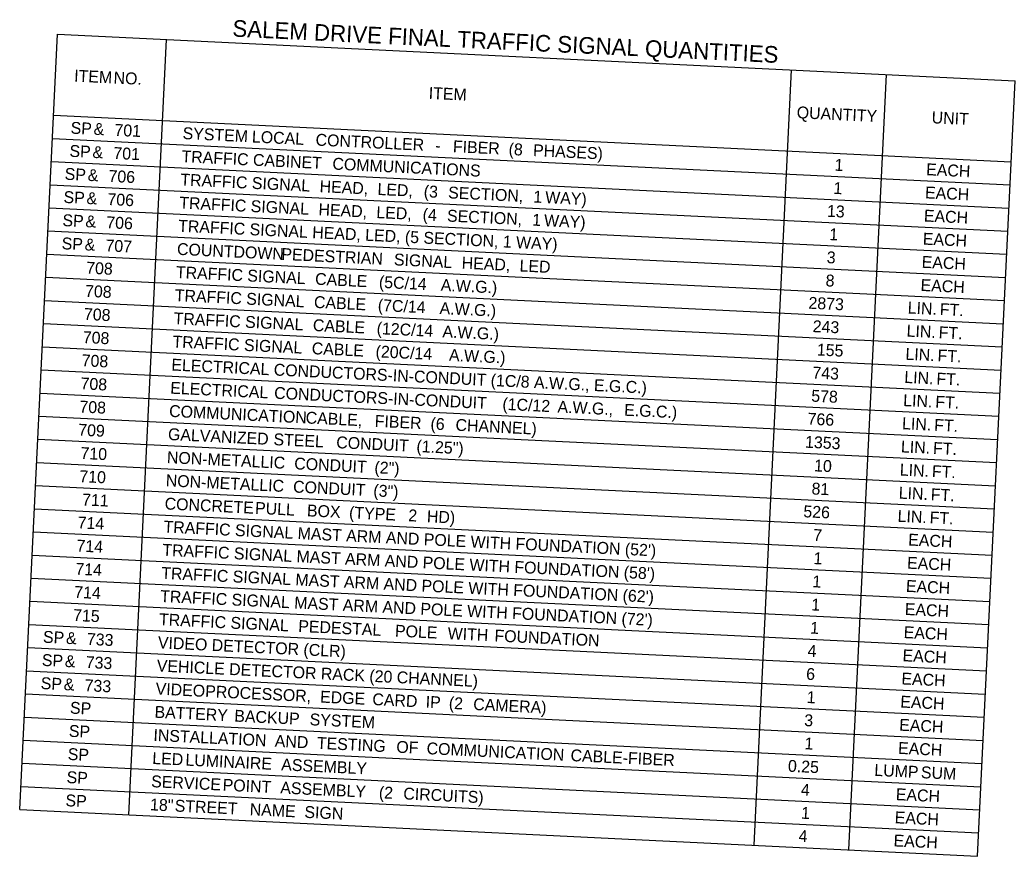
# Model space of a CAD drawing. Extents: x 661018 to 663325, y 642537 to 643074.
# Drawn here: x 661242.6 to 661445.4, y 642615.8 to 642786.2 of the extents above; entities that cross this region are included whole.
import ezdxf

# ---------------------------------------------------------------- set-up
doc = ezdxf.new("R2010")
doc.units = 0
doc.layers.add('R_Border Notes', color=7, linetype='Continuous')

msp = doc.modelspace()

# ---------------------------------------------------------------- linework, layer by layer
at = {"layer": 'R_Border Notes'}
for p, q in [((661242.61, 642625.3), (661250.28, 642783.32)), ((661250.28, 642783.32), (661445.37, 642773.84)), ((661264.78, 642624.22), (661272.45, 642782.24)), ((661392.18, 642618.03), (661399.85, 642776.05)), ((661411.52, 642617.09), (661419.19, 642775.11)), ((661437.7, 642615.82), (661445.37, 642773.84)), ((661249.48, 642766.81), (661444.57, 642757.33)), ((661249.25, 642762.09), (661444.34, 642752.62)), ((661249.02, 642757.37), (661444.11, 642747.9)), ((661248.79, 642752.65), (661443.88, 642743.18)), ((661248.56, 642747.94), (661443.65, 642738.46)), ((661248.33, 642743.22), (661443.43, 642733.75)), ((661248.11, 642738.5), (661443.2, 642729.03)), ((661247.88, 642733.79), (661442.97, 642724.31)), ((661247.65, 642729.07), (661442.74, 642719.6)), ((661247.42, 642724.35), (661442.51, 642714.88)), ((661247.19, 642719.64), (661442.28, 642710.16)), ((661246.96, 642714.92), (661442.05, 642705.45)), ((661246.73, 642710.2), (661441.82, 642700.73)), ((661246.5, 642705.48), (661441.59, 642696.01)), ((661246.27, 642700.77), (661441.36, 642691.29)), ((661246.04, 642696.05), (661441.14, 642686.58)), ((661245.82, 642691.33), (661440.91, 642681.86)), ((661245.59, 642686.62), (661440.68, 642677.14)), ((661245.36, 642681.9), (661440.45, 642672.43)), ((661245.13, 642677.18), (661440.22, 642667.71)), ((661244.9, 642672.47), (661439.99, 642662.99)), ((661244.67, 642667.75), (661439.76, 642658.28)), ((661244.44, 642663.03), (661439.53, 642653.56)), ((661244.21, 642658.31), (661439.3, 642648.84)), ((661243.98, 642653.6), (661439.07, 642644.12)), ((661243.75, 642648.88), (661438.84, 642639.41)), ((661243.52, 642644.16), (661438.62, 642634.69)), ((661243.3, 642639.45), (661438.39, 642629.97)), ((661243.07, 642634.73), (661438.16, 642625.26)), ((661242.84, 642630.01), (661437.93, 642620.54)), ((661242.61, 642625.3), (661437.7, 642615.82))]:
    msp.add_line(p, q, dxfattribs=at)

# ---------------------------------------------------------------- texts
for s, height, p in [('SALEM DRIVE FINAL TRAFFIC SIGNAL QUANTITIES', 3.3906, (661285.85, 642782.85)), ('ITEM', 2.422, (661253.62, 642773.67)), (' NO.', 2.422, (661260.75, 642773.32)), ('ITEM', 2.422, (661325.86, 642770.16)), ('QUANTITY', 2.422, (661400.84, 642766.21)), ('UNIT', 2.422, (661428.33, 642765.18)), ('SP', 2.422, (661252.9, 642763.06)), (' &', 2.422, (661256.69, 642762.88)), (' 701', 2.422, (661260.93, 642762.67)), ('SYSTEM', 2.422, (661275.72, 642761.96)), (' LOCAL', 2.422, (661288.94, 642761.31)), (' CONTROLLER', 2.4218, (661301.91, 642760.68)), ('SP', 2.422, (661252.67, 642758.35)), (' &', 2.422, (661256.46, 642758.16)), (' 701', 2.422, (661260.71, 642757.96)), (' -', 2.422, (661326.29, 642759.5)), (' FIBER', 2.422, (661329.89, 642759.32)), (' (8', 2.422, (661341.24, 642758.77)), (' PHASES)', 2.422, (661346.22, 642758.53)), ('TRAFFIC', 2.422, (661275.49, 642757.24)), (' CABINET', 2.422, (661289.15, 642756.58)), (' COMMUNICATIONS', 2.4218, (661305.34, 642755.79)), ('SP', 2.422, (661251.69, 642753.67)), ('1', 2.42, (661408.55, 642755.51)), ('EACH', 2.422, (661427.21, 642754.6)), (' &', 2.422, (661255.48, 642753.48)), (' 706', 2.422, (661259.72, 642753.28)), ('TRAFFIC', 2.422, (661275.26, 642752.52)), (' SIGNAL', 2.422, (661288.92, 642751.86)), (' HEAD,', 2.422, (661302.73, 642751.19)), (' LED,', 2.422, (661314.52, 642750.61)), (' (3', 2.422, (661323.95, 642750.16)), (' SECTION,', 2.422, (661328.92, 642749.92)), ('1', 2.42, (661408.32, 642750.79)), ('EACH', 2.422, (661426.98, 642749.88)), ('SP', 2.422, (661251.46, 642748.95)), (' &', 2.422, (661255.25, 642748.77)), (' 706', 2.422, (661259.5, 642748.56)), ('TRAFFIC', 2.422, (661275.04, 642747.8)), (' 1', 2.422, (661346.27, 642749.07)), (' WAY)', 2.422, (661348.69, 642748.96)), (' SIGNAL', 2.422, (661288.69, 642747.14)), (' HEAD,', 2.422, (661302.5, 642746.47)), (' LED,', 2.422, (661314.29, 642745.9)), ('13', 2.422, (661407, 642746.12)), ('SP', 2.422, (661251.23, 642744.23)), (' &', 2.422, (661255.02, 642744.05)), (' 706', 2.422, (661259.27, 642743.84)), (' (4', 2.422, (661323.72, 642745.44)), (' SECTION,', 2.422, (661328.69, 642745.2)), (' 1', 2.422, (661346.04, 642744.36)), (' WAY)', 2.422, (661348.46, 642744.24)), ('EACH', 2.422, (661426.75, 642745.16)), ('TRAFFIC SIGNAL HEAD, LED, (5 SECTION, 1 WAY)', 2.4218, (661274.81, 642743.09)), ('SP', 2.422, (661251.07, 642739.51)), ('1', 2.42, (661407.46, 642741.37)), ('EACH', 2.422, (661426.53, 642740.45)), (' &', 2.422, (661254.86, 642739.33)), (' 707', 2.422, (661259.1, 642739.12)), ('COUNTDOWN', 2.422, (661274.58, 642738.37)), (' PEDESTRIAN', 2.4218, (661294.94, 642737.38)), (' SIGNAL', 2.422, (661317.87, 642736.27)), (' HEAD,', 2.422, (661331.68, 642735.6)), ('3', 2.42, (661406.95, 642736.67)), ('EACH', 2.422, (661426.3, 642735.73)), ('708', 2.422, (661256.07, 642734.54)), ('TRAFFIC', 2.422, (661274.35, 642733.65)), (' LED', 2.422, (661343.47, 642735.02)), (' SIGNAL', 2.422, (661288, 642732.99)), (' CABLE', 2.422, (661301.81, 642732.32)), (' (5C/14', 2.422, (661314.82, 642731.69)), ('8', 2.42, (661406.72, 642731.95)), ('708', 2.422, (661255.84, 642729.82)), (' A.W.G.)', 2.422, (661327.41, 642731.08)), ('EACH', 2.422, (661426.07, 642731.01)), ('TRAFFIC', 2.422, (661274.12, 642728.94)), (' SIGNAL', 2.422, (661287.78, 642728.27)), (' CABLE', 2.422, (661301.58, 642727.6)), ('2873', 2.422, (661403.23, 642727.39)), (' (7C/14', 2.422, (661314.59, 642726.97)), (' A.W.G.)', 2.422, (661327.18, 642726.36)), ('LIN.', 2.422, (661423.45, 642726.41)), (' FT.', 2.422, (661429.09, 642726.14)), ('708', 2.422, (661255.61, 642725.11)), ('TRAFFIC', 2.422, (661273.89, 642724.22)), (' SIGNAL', 2.422, (661287.55, 642723.56)), (' CABLE', 2.422, (661301.36, 642722.89)), (' (12C/14', 2.422, (661314.36, 642722.25)), (' A.W.G.)', 2.422, (661327.76, 642721.6)), ('243', 2.422, (661404.09, 642722.62)), ('LIN.', 2.422, (661423.22, 642721.7)), (' FT.', 2.422, (661428.86, 642721.42)), ('708', 2.422, (661255.38, 642720.39)), ('TRAFFIC', 2.422, (661273.66, 642719.5)), (' SIGNAL', 2.422, (661287.32, 642718.84)), (' CABLE', 2.422, (661301.13, 642718.17)), (' (20C/14', 2.422, (661314.14, 642717.54)), ('155', 2.422, (661404.94, 642717.86)), ('708', 2.422, (661255.15, 642715.67)), (' A.W.G.)', 2.422, (661329.09, 642716.81)), ('LIN.', 2.422, (661422.99, 642716.98)), (' FT.', 2.422, (661428.63, 642716.71)), ('ELECTRICAL CONDUCTORS-IN-CONDUIT (1C/8 A.W.G., E.G.C.)', 2.4218, (661273.43, 642714.79)), ('743', 2.422, (661404.03, 642713.17)), ('LIN.', 2.422, (661422.76, 642712.26)), (' FT.', 2.422, (661428.4, 642711.99)), ('708', 2.422, (661254.92, 642710.96)), ('ELECTRICAL', 2.422, (661273.2, 642710.07)), (' CONDUCTORS-IN-CONDUIT', 2.4218, (661293.47, 642709.08)), ('578', 2.422, (661403.8, 642708.45)), ('LIN.', 2.422, (661422.53, 642707.54)), (' FT.', 2.422, (661428.17, 642707.27)), ('708', 2.422, (661254.69, 642706.24)), ('COMMUNICATION', 2.4218, (661272.97, 642705.35)), (' (1C/12', 2.422, (661339.98, 642706.83)), (' A.W.G.,', 2.422, (661351.2, 642706.28)), (' E.G.C.)', 2.422, (661364.78, 642705.62)), (' CABLE,', 2.422, (661299.89, 642704.04)), (' FIBER', 2.422, (661313.96, 642703.36)), ('766', 2.422, (661403.05, 642703.76)), ('709', 2.422, (661254.45, 642701.52)), (' (6', 2.422, (661325.32, 642702.81)), (' CHANNEL)', 2.422, (661330.42, 642702.56)), ('LIN.', 2.422, (661422.3, 642702.83)), (' FT.', 2.422, (661427.94, 642702.55)), ('GALVANIZED', 2.422, (661272.74, 642700.63)), (' STEEL', 2.422, (661293.33, 642699.63)), (' CONDUIT', 2.422, (661306.12, 642699.01)), ('1353', 2.422, (661402.54, 642699.06)), (' (1.25")', 2.422, (661322.46, 642698.22)), ('LIN.', 2.422, (661422.07, 642698.11)), (' FT.', 2.422, (661427.71, 642697.84)), ('710', 2.422, (661254.91, 642696.77)), ('NON-METALLIC', 2.4218, (661272.52, 642695.92)), (' CONDUIT', 2.422, (661297.56, 642694.7)), (' (2")', 2.422, (661313.9, 642693.91)), ('10', 2.422, (661404.38, 642694.24)), ('LIN.', 2.422, (661421.84, 642693.39)), (' FT.', 2.422, (661427.48, 642693.12)), ('710', 2.422, (661254.68, 642692.05)), ('NON-METALLIC', 2.4218, (661272.29, 642691.2)), (' CONDUIT', 2.422, (661297.33, 642689.98)), (' (3")', 2.422, (661313.68, 642689.19)), ('81', 2.422, (661403.86, 642689.54)), ('711', 2.422, (661255.24, 642687.3)), ('LIN.', 2.422, (661421.62, 642688.68)), (' FT.', 2.422, (661427.25, 642688.4)), ('CONCRETE', 2.422, (661272.06, 642686.48)), (' PULL', 2.422, (661289.58, 642685.63)), (' BOX', 2.422, (661300.15, 642685.12)), (' (TYPE', 2.422, (661308.74, 642684.7)), ('526', 2.422, (661402.19, 642684.89)), (' 2', 2.422, (661320.8, 642684.12)), (' HD)', 2.422, (661324.59, 642683.93)), ('LIN.', 2.422, (661421.39, 642683.96)), (' FT.', 2.422, (661427.02, 642683.69)), ('714', 2.422, (661254.33, 642682.62)), ("TRAFFIC SIGNAL MAST ARM AND POLE WITH FOUNDATION (52')", 2.4218, (661271.83, 642681.77)), ('7', 2.42, (661404.2, 642680.07)), ('EACH', 2.422, (661423.55, 642679.13)), ('714', 2.422, (661254.1, 642677.9)), ("TRAFFIC SIGNAL MAST ARM AND POLE WITH FOUNDATION (58')", 2.4218, (661271.6, 642677.05)), ('1', 2.42, (661404.25, 642675.34)), ('714', 2.422, (661253.87, 642673.18)), ('EACH', 2.422, (661423.32, 642674.41)), ("TRAFFIC SIGNAL MAST ARM AND POLE WITH FOUNDATION (62')", 2.4218, (661271.37, 642672.33)), ('1', 2.42, (661404.03, 642670.62)), ('EACH', 2.422, (661423.09, 642669.69)), ('714', 2.422, (661253.64, 642668.46)), ("TRAFFIC SIGNAL MAST ARM AND POLE WITH FOUNDATION (72')", 2.4218, (661271.14, 642667.62)), ('1', 2.42, (661403.8, 642665.9)), ('EACH', 2.422, (661422.86, 642664.98)), ('715', 2.422, (661253.41, 642663.75)), ('TRAFFIC', 2.422, (661270.91, 642662.9)), (' SIGNAL', 2.422, (661284.57, 642662.23)), (' PEDESTAL', 2.422, (661298.38, 642661.56)), (' POLE', 2.422, (661318.09, 642660.61)), ('1', 2.42, (661403.57, 642661.18)), ('SP', 2.422, (661247.27, 642659.32)), (' &', 2.422, (661251.06, 642659.13)), (' 733', 2.422, (661255.31, 642658.93)), (' WITH', 2.422, (661328.82, 642660.09)), (' FOUNDATION', 2.4218, (661338.36, 642659.62)), ('EACH', 2.422, (661422.63, 642660.26)), ('VIDEO DETECTOR (CLR)', 2.4218, (661270.68, 642658.18)), ('4', 2.42, (661403.05, 642656.48)), ('SP', 2.422, (661247.04, 642654.6)), (' &', 2.422, (661250.83, 642654.42)), ('EACH', 2.422, (661422.4, 642655.54)), (' 733', 2.422, (661255.08, 642654.21)), ('VEHICLE DETECTOR RACK (20 CHANNEL)', 2.4218, (661270.45, 642653.46)), ('6', 2.42, (661402.76, 642651.77)), ('EACH', 2.422, (661422.17, 642650.82)), ('SP', 2.422, (661246.81, 642649.88)), (' &', 2.422, (661250.6, 642649.7)), (' 733', 2.422, (661254.85, 642649.49)), ('VIDEO', 2.422, (661270.22, 642648.75)), (' PROCESSOR,', 2.4218, (661279.42, 642648.3)), (' EDGE', 2.422, (661302.83, 642647.16)), (' CARD', 2.422, (661313.48, 642646.65)), ('1', 2.42, (661402.88, 642647.03)), ('SP', 2.422, (661252.77, 642644.87)), (' IP', 2.422, (661324.34, 642646.12)), (' (2', 2.422, (661329.06, 642645.89)), (' CAMERA)', 2.422, (661334.03, 642645.65)), ('EACH', 2.422, (661421.94, 642646.11)), ('BATTERY', 2.422, (661270, 642644.03)), (' BACKUP', 2.422, (661285.35, 642643.28)), (' SYSTEM', 2.422, (661300.7, 642642.54)), ('3', 2.42, (661402.37, 642642.33)), ('SP', 2.422, (661252.54, 642640.15)), ('EACH', 2.422, (661421.72, 642641.39)), ('INSTALLATION', 2.4218, (661269.77, 642639.31)), (' AND', 2.422, (661293.59, 642638.16)), (' TESTING', 2.422, (661302.17, 642637.74)), (' OF', 2.422, (661318.36, 642636.95)), (' COMMUNICATION', 2.4218, (661324.53, 642636.65)), ('1', 2.42, (661402.42, 642637.6)), ('EACH', 2.422, (661421.49, 642636.67)), ('SP', 2.422, (661252.31, 642635.43)), ('LED', 2.422, (661269.54, 642634.6)), (' LUMINAIRE', 2.422, (661275.39, 642634.31)), (' CABLE-FIBER', 2.4218, (661353.86, 642635.23)), (' ASSEMBLY', 2.422, (661294.91, 642633.36)), ('0.25', 2.422, (661399.05, 642633.03)), ('LUMP', 2.422, (661416.65, 642632.18)), ('SP', 2.422, (661252.08, 642630.72)), (' SUM', 2.422, (661425.24, 642631.76)), ('SERVICE', 2.422, (661269.31, 642629.88)), (' POINT', 2.422, (661282.98, 642629.21)), (' ASSEMBLY', 2.422, (661294.72, 642628.64)), ('4', 2.42, (661401.68, 642628.18)), ('SP', 2.422, (661251.85, 642626)), (' (2', 2.422, (661314.81, 642627.67)), (' CIRCUITS)', 2.422, (661319.78, 642627.43)), ('EACH', 2.422, (661421.03, 642627.24)), ('18"', 2.422, (661269.08, 642625.16)), (' STREET', 2.422, (661273.21, 642624.96)), (' NAME', 2.422, (661288.49, 642624.22)), (' SIGN', 2.422, (661299.63, 642623.68)), ('1', 2.42, (661401.73, 642623.45)), ('EACH', 2.422, (661420.8, 642622.52)), ('4', 2.42, (661401.22, 642618.75)), ('EACH', 2.422, (661420.57, 642617.81))]:
    msp.add_text(s, height=height, rotation=357.2199, dxfattribs=at).set_placement(p)

doc.saveas('drawing.dxf')
